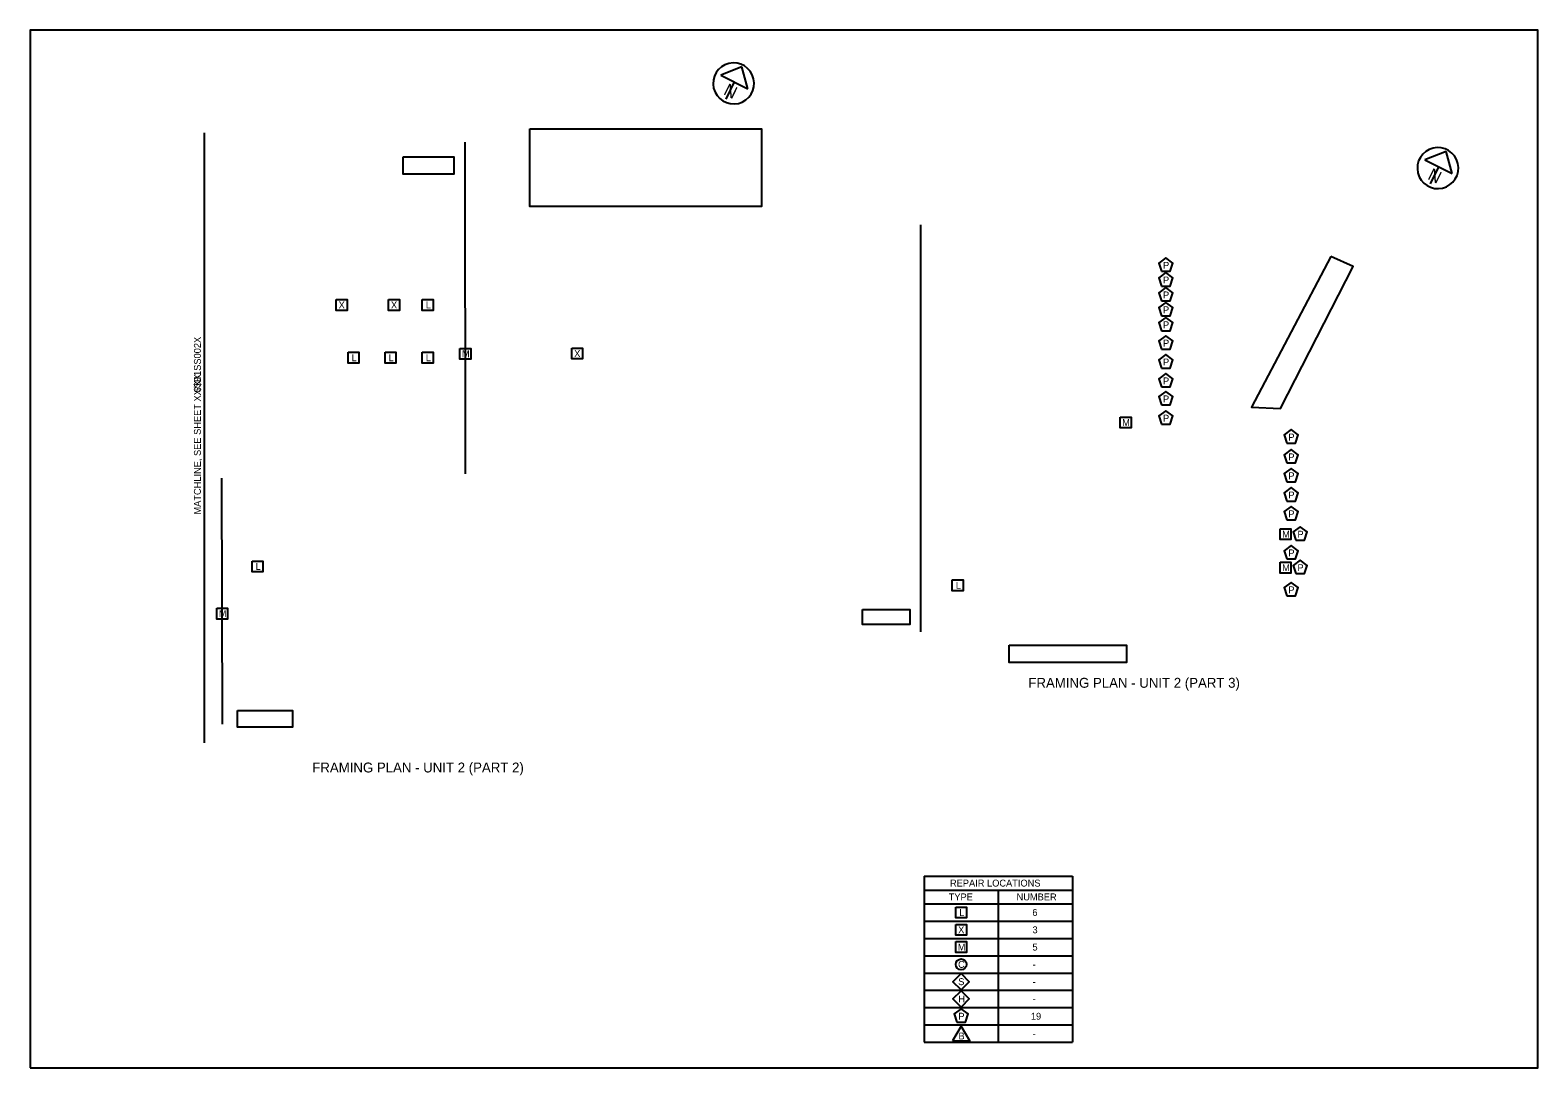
# Model space of a CAD drawing. Extents: x 100 to 130.5, y 100 to 121.
import ezdxf

# ---------------------------------------------------------------- set-up
doc = ezdxf.new("R2010")
doc.units = 0
for name, color, linetype in [('BR_P_Gen_Text', 7, 'Continuous'), ('BR_X_Sub_Centerline', 7, 'Continuous'), ('BR_X_Sub_Text', 7, 'Continuous'), ('SC_Scratch1', 7, 'Continuous'), ('SH_Data', 7, 'Continuous'), ('SH_Masking', 7, 'Continuous')]:
    doc.layers.add(name, color=color, linetype=linetype)

msp = doc.modelspace()

# ---------------------------------------------------------------- linework, layer by layer
at = {"layer": 'BR_P_Gen_Text'}
for p, q in [((103.523, 118.922), (103.523, 106.578)), ((118.083, 103.879), (118.083, 100.519)), ((118.083, 103.879), (121.083, 103.879)), ((121.083, 103.879), (121.083, 100.519)), ((118.083, 103.599), (121.083, 103.599)), ((119.583, 103.599), (119.583, 100.519)), ((118.083, 103.319), (121.083, 103.319)), ((118.083, 102.969), (121.083, 102.969)), ((118.083, 102.619), (121.083, 102.619)), ((118.083, 102.269), (121.083, 102.269)), ((118.083, 101.919), (121.083, 101.919)), ((118.083, 101.569), (121.083, 101.569)), ((118.083, 101.219), (121.083, 101.219)), ((118.083, 100.869), (121.083, 100.869)), ((118.083, 100.519), (121.083, 100.519))]:
    msp.add_line(p, q, dxfattribs=at)
for points in [[(122.885, 116.12), (123.062, 116.12), (123.116, 116.287), (122.973, 116.391), (122.831, 116.287)], [(122.885, 115.821), (123.062, 115.821), (123.116, 115.989), (122.973, 116.093), (122.831, 115.989)], [(122.885, 115.519), (123.062, 115.519), (123.116, 115.687), (122.973, 115.791), (122.831, 115.687)], [(106.191, 115.549), (106.411, 115.549), (106.411, 115.329), (106.191, 115.329)], [(107.249, 115.549), (107.469, 115.549), (107.469, 115.329), (107.249, 115.329)], [(107.931, 115.549), (108.151, 115.549), (108.151, 115.329), (107.931, 115.329)], [(122.885, 115.218), (123.062, 115.218), (123.116, 115.386), (122.973, 115.49), (122.831, 115.386)], [(122.885, 114.915), (123.062, 114.915), (123.116, 115.083), (122.973, 115.186), (122.831, 115.083)], [(122.885, 114.545), (123.062, 114.545), (123.116, 114.712), (122.973, 114.816), (122.831, 114.712)], [(106.43, 114.48), (106.65, 114.48), (106.65, 114.26), (106.43, 114.26)], [(107.179, 114.48), (107.399, 114.48), (107.399, 114.26), (107.179, 114.26)], [(107.931, 114.48), (108.151, 114.48), (108.151, 114.26), (107.931, 114.26)], [(108.693, 114.56), (108.913, 114.56), (108.913, 114.34), (108.693, 114.34)], [(110.957, 114.565), (111.177, 114.565), (111.177, 114.345), (110.957, 114.345)], [(122.885, 114.162), (123.062, 114.162), (123.116, 114.33), (122.973, 114.434), (122.831, 114.33)], [(122.885, 113.78), (123.062, 113.78), (123.116, 113.947), (122.973, 114.051), (122.831, 113.947)], [(122.885, 113.416), (123.062, 113.416), (123.116, 113.583), (122.973, 113.687), (122.831, 113.583)], [(122.05, 113.169), (122.27, 113.169), (122.27, 112.949), (122.05, 112.949)], [(122.885, 113.025), (123.062, 113.025), (123.116, 113.193), (122.973, 113.297), (122.831, 113.193)], [(125.421, 112.644), (125.597, 112.644), (125.652, 112.812), (125.509, 112.915), (125.366, 112.812)], [(125.421, 112.241), (125.597, 112.241), (125.652, 112.409), (125.509, 112.513), (125.366, 112.409)], [(125.421, 111.859), (125.597, 111.859), (125.652, 112.027), (125.509, 112.131), (125.366, 112.027)], [(125.421, 111.471), (125.597, 111.471), (125.652, 111.639), (125.509, 111.743), (125.366, 111.639)], [(125.421, 111.089), (125.597, 111.089), (125.652, 111.257), (125.509, 111.361), (125.366, 111.257)], [(125.286, 110.909), (125.506, 110.909), (125.506, 110.689), (125.286, 110.689)], [(125.605, 110.677), (125.781, 110.677), (125.836, 110.845), (125.693, 110.949), (125.55, 110.845)], [(125.421, 110.299), (125.597, 110.299), (125.652, 110.466), (125.509, 110.57), (125.366, 110.466)], [(104.489, 110.257), (104.709, 110.257), (104.709, 110.037), (104.489, 110.037)], [(125.286, 110.232), (125.506, 110.232), (125.506, 110.012), (125.286, 110.012)], [(125.605, 110.001), (125.781, 110.001), (125.836, 110.168), (125.693, 110.272), (125.55, 110.168)], [(118.653, 109.874), (118.873, 109.874), (118.873, 109.654), (118.653, 109.654)], [(125.421, 109.552), (125.597, 109.552), (125.652, 109.72), (125.509, 109.823), (125.366, 109.72)], [(103.775, 109.302), (103.995, 109.302), (103.995, 109.082), (103.775, 109.082)], [(118.723, 103.254), (118.943, 103.254), (118.943, 103.034), (118.723, 103.034)], [(118.723, 102.904), (118.943, 102.904), (118.943, 102.684), (118.723, 102.684)], [(118.723, 102.554), (118.943, 102.554), (118.943, 102.334), (118.723, 102.334)], [(118.833, 101.909), (118.998, 101.744), (118.833, 101.579), (118.668, 101.744)], [(118.833, 101.559), (118.998, 101.394), (118.833, 101.229), (118.668, 101.394)], [(118.745, 100.923), (118.922, 100.923), (118.976, 101.091), (118.833, 101.194), (118.691, 101.091)], [(118.66, 100.544), (119.007, 100.544), (118.833, 100.844)]]:
    msp.add_lwpolyline(points, close=True, dxfattribs=at)
msp.add_circle((118.833, 102.094), 0.11, dxfattribs=at)
at = {"layer": 'BR_X_Sub_Centerline'}
for p, q in [((108.794, 118.73), (108.802, 112.021)), ((118.021, 108.826), (118.02, 117.062)), ((103.891, 106.958), (103.879, 111.931))]:
    msp.add_line(p, q, dxfattribs=at)
at = {"layer": 'BR_X_Sub_Text'}
for points in [[(107.548, 118.434), (108.573, 118.434), (108.573, 118.084), (107.548, 118.084)], [(116.835, 109.278), (117.797, 109.278), (117.797, 108.973), (116.835, 108.973)], [(104.196, 107.235), (105.306, 107.235), (105.306, 106.893), (104.196, 106.893)]]:
    msp.add_lwpolyline(points, close=True, dxfattribs=at)
at = {"layer": 'SC_Scratch1'}
msp.add_lwpolyline([(100, 100), (130.5, 100), (130.5, 121), (100, 121)], close=True, dxfattribs=at)
at = {"layer": 'SH_Data'}
for p, q in [((114.397, 120.257), (113.97, 120.088)), ((114.521, 119.814), (114.397, 120.257)), ((113.97, 120.088), (114.521, 119.814)), ((114.245, 119.951), (114.073, 119.605)), ((128.644, 118.542), (128.216, 118.374)), ((128.216, 118.374), (128.767, 118.1)), ((128.767, 118.1), (128.644, 118.542)), ((128.491, 118.237), (128.319, 117.89))]:
    msp.add_line(p, q, dxfattribs=at)
for centre in [(114.231, 119.922), (128.477, 118.208)]:
    msp.add_arc(centre, 0.415, 103.3206, 103.3041, dxfattribs=at)
at = {"layer": 'SH_Masking'}
for points in [[(110.107, 119.001), (114.798, 119.001), (114.798, 117.428), (110.107, 117.428)], [(126.31, 116.422), (124.71, 113.372), (125.297, 113.345), (126.766, 116.22)], [(119.805, 108.552), (122.179, 108.552), (122.179, 108.204), (119.805, 108.204)]]:
    msp.add_lwpolyline(points, close=True, dxfattribs=at)

# ---------------------------------------------------------------- texts
at = {"layer": 'BR_P_Gen_Text'}
for s, height, p in [('P', 0.14, (122.917, 116.171)), ('P', 0.14, (122.917, 115.873)), ('P', 0.14, (122.917, 115.571)), ('X', 0.14, (106.24, 115.369)), ('X', 0.14, (107.299, 115.369)), ('L', 0.14, (108.003, 115.369)), ('P', 0.14, (122.917, 115.27)), ('P', 0.14, (122.917, 114.966)), ('P', 0.14, (122.917, 114.596)), ('L', 0.14, (106.502, 114.3)), ('L', 0.14, (107.251, 114.3)), ('L', 0.14, (108.003, 114.3)), ('M', 0.14, (108.735, 114.38)), ('X', 0.14, (111.006, 114.385)), ('P', 0.14, (122.917, 114.214)), ('P', 0.14, (122.917, 113.831)), ('P', 0.14, (122.917, 113.467)), ('P', 0.14, (122.917, 113.077)), ('M', 0.14, (122.091, 112.989)), ('P', 0.14, (125.453, 112.695)), ('P', 0.14, (125.453, 112.293)), ('P', 0.14, (125.453, 111.911)), ('P', 0.14, (125.453, 111.523)), ('P', 0.14, (125.453, 111.141)), ('M', 0.14, (125.327, 110.729)), ('P', 0.14, (125.637, 110.729)), ('P', 0.14, (125.453, 110.35)), ('L', 0.14, (104.561, 110.077)), ('M', 0.14, (125.327, 110.052)), ('P', 0.14, (125.637, 110.052)), ('L', 0.14, (118.725, 109.694)), ('P', 0.14, (125.453, 109.603)), ('M', 0.14, (103.816, 109.122)), ('FRAMING PLAN - UNIT 2 (PART 3)', 0.2, (120.193, 107.692)), ('FRAMING PLAN - UNIT 2 (PART 2)', 0.2, (105.707, 105.978)), ('REPAIR LOCATIONS', 0.14, (118.608, 103.669)), ('TYPE', 0.14, (118.582, 103.389)), ('NUMBER', 0.14, (119.955, 103.389)), ('L', 0.14, (118.795, 103.074)), ('6', 0.14, (120.274, 103.074)), ('X', 0.14, (118.773, 102.724)), ('3', 0.14, (120.277, 102.724)), ('M', 0.14, (118.765, 102.374)), ('5', 0.14, (120.276, 102.374)), ('C', 0.14, (118.771, 102.024)), ('-', 0.14, (120.28, 102.024)), ('S', 0.14, (118.775, 101.674)), ('-', 0.14, (120.28, 101.674)), ('H', 0.14, (118.777, 101.324)), ('-', 0.14, (120.28, 101.324)), ('P', 0.14, (118.777, 100.974)), ('19', 0.14, (120.244, 100.974)), ('B', 0.14, (118.779, 100.574)), ('-', 0.14, (120.28, 100.624))]:
    msp.add_text(s, height=height, dxfattribs=at).set_placement(p)
for s, p in [('$$B1SS002X', (103.453, 113.669)), ('MATCHLINE, SEE SHEET XX/XX', (103.453, 111.197))]:
    msp.add_text(s, height=0.14, rotation=90, dxfattribs=at).set_placement(p)
at = {"layer": 'SH_Data'}
for p in [(114.008, 119.708), (128.254, 117.993)]:
    msp.add_text('N', height=0.25, rotation=333.5408, dxfattribs=at).set_placement(p)

doc.saveas('drawing.dxf')
